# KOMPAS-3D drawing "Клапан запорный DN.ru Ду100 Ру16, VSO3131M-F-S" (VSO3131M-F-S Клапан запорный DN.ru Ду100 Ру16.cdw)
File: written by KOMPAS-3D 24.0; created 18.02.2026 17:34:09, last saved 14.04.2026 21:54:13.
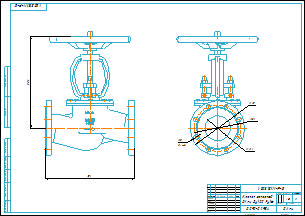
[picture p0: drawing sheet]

Document properties: Автор: R2D2; Форматы листов документа: A2; Полное имя файла: VSO3131M-F-S Клапан запорный DN.ru Ду100 Ру16.m3d; Масса: 26; Наименование: Клапан запорный DN.ru Ду100 Ру16; Количество листов документа: 1; Примечание: D090-02954

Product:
- Part/product: Клапан запорный DN.ru Ду100 Ру16  | designation VSO3131M-F-S
    Масса: 26
    Раздел спецификации: Прочие изделия
    Примечание: D090-02954

Views: Вид 1, Спереди, Проекционный вид 2
Referenced files in E:\Работа\Зайцев\VSO3131M-F-S Клапан запорный DN.ru Ду15-100 Ру40\DN50\: VSO3131M-F-S Клапан запорный DN.ru Ду50 Ру40.m3d
Referenced files in E:\Работа\Зайцев\VSO3131M-F-S Клапан запорный DN.ru Ду15-100 Ру16\DN100\: VSO3131M-F-S Клапан запорный DN.ru Ду100 Ру16.m3d
Referenced files in E:\Работа\Зайцев\Для компаса\: чертеж DN.ru А3.cdt
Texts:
  VSO3131M-F-S
  чертеж DN.ru А3.cdt
  Клапан запорный
  DN.ru Ду100 Ру16
  Клапан запорный DN.ru Ду100 Ру16
  VSO3131M-F-S Клапан запорный DN.ru Ду100 Ру16
Dimensions and other numbers on the sheet: 0; 3; 2; 4; 350; 360; 18; 8 отв.; 215; 180; 100; 1:2; 1; 26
